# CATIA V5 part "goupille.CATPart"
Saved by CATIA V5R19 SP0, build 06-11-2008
Part number: goupille
Bounding box of the stored display mesh (mm): x 0 to 20, y -4 to 4, z -3.804 to 3.804
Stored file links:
  C:\Documents and Settings\alenoir\Bureau\mécanisme\goupille.CATPart
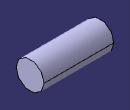
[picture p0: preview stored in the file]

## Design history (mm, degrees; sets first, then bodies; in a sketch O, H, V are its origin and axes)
Body1 (main body)
  Sketch1 on yz-plane, origin (0, 0, 0), H (0, 1, 0), V (0, 0, 1)
    circle A1 centre (0, 0) radius 4
    radius A1 = 4
  Pad1: profile Sketch1, direction (1, 0, 0), length 20
  Sketch2 on start face of Pad1, origin (0, 0, 0), H (0, 1, 0), V (0, 0, 1)
    circle A1 centre (0, 0) radius 4
    radius A1 = 4
  Pad2: profile Sketch2, direction (1, 0, 0), length 20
